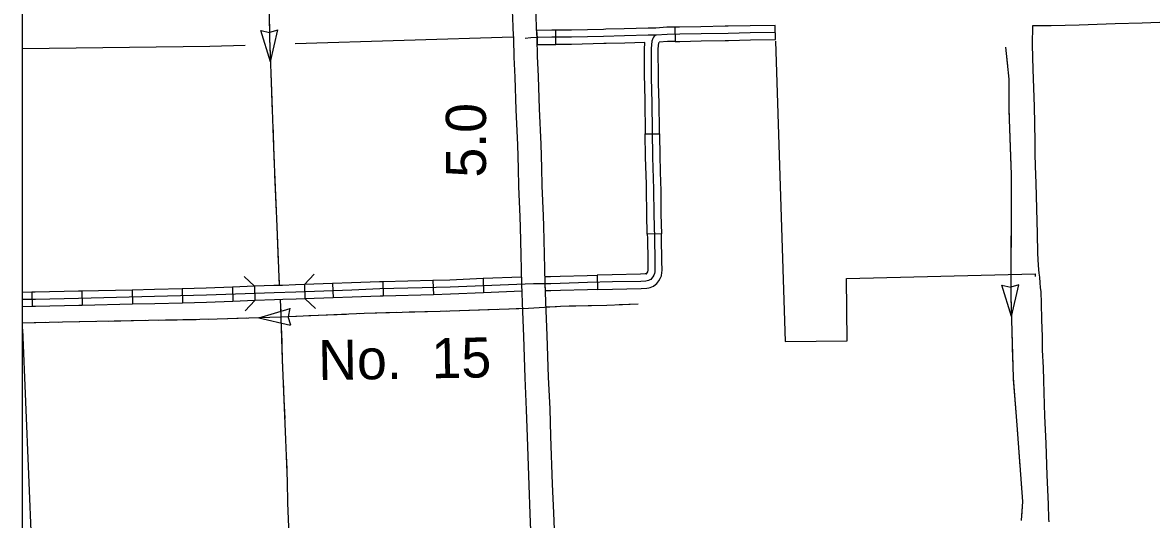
# Model space of a CAD drawing. Extents: x -117616 to 64730, y 54117 to 789866.
# Drawn here: x 62347.4 to 62585, y 54731.4 to 54836.1 of the extents above; entities that cross this region are included whole.
import ezdxf

# ---------------------------------------------------------------- set-up
doc = ezdxf.new("R2010")
doc.units = 0
for name, color, linetype in [('10', 7, 'Continuous'), ('31', 7, 'Continuous'), ('32', 7, 'Continuous'), ('33', 7, 'Continuous'), ('34', 7, 'Continuous'), ('38', 7, 'Continuous'), ('43', 7, 'Continuous'), ('48', 7, 'Continuous'), ('5', 7, 'Continuous'), ('6', 7, 'Continuous'), ('R_No Plot', 7, 'Continuous')]:
    doc.layers.add(name, color=color, linetype=linetype)

msp = doc.modelspace()

# ---------------------------------------------------------------- linework, layer by layer
at = {"layer": '10'}
for points in [[(62455.71, 54832.86), (62455.58, 54834.94), (62455.49, 54837.59), (62455.42, 54838.97), (62455.39, 54840.33), (62455.28, 54843.01), (62455.03, 54848.86), (62454.92, 54851.89), (62454.84, 54854.63), (62454.71, 54858.54), (62454.57, 54861.37), (62454.52, 54862.77)], [(62449.52, 54862.7), (62449.57, 54861.27), (62449.71, 54858.44), (62449.84, 54854.59), (62449.92, 54851.84), (62450.03, 54848.78), (62450.28, 54842.91), (62450.39, 54840.27), (62450.42, 54838.88), (62450.5, 54837.49), (62450.58, 54834.82), (62450.72, 54832.66)], [(62450.72, 54832.66), (62450.82, 54828.83), (62451.01, 54824.59), (62451.2, 54817.72), (62451.56, 54810.33), (62451.72, 54805.37), (62451.8, 54801.59), (62452.05, 54795.2), (62452.15, 54793.02), (62452.29, 54787.22), (62452.44, 54781.04)], [(62457.44, 54781.17), (62457.29, 54787.34), (62457.15, 54793.2), (62457.04, 54795.42), (62456.8, 54801.74), (62456.72, 54805.5), (62456.55, 54810.53), (62456.2, 54817.91), (62456.01, 54824.77), (62455.82, 54829.01), (62455.71, 54832.86)], [(62452.44, 54781.04), (62452.66, 54775.25), (62452.87, 54769.99), (62453.13, 54761.25), (62453.43, 54754.52), (62453.61, 54748.81), (62453.97, 54738.69), (62454.21, 54732.61), (62454.41, 54727.36)], [(62459.41, 54727.55), (62459.21, 54732.81), (62458.97, 54738.88), (62458.61, 54748.98), (62458.43, 54754.71), (62458.13, 54761.44), (62457.86, 54770.17), (62457.65, 54775.44), (62457.44, 54781.17)]]:
    msp.add_lwpolyline(points, dxfattribs=at)
at = {"layer": '31'}
for p, q in [((62459.63, 54831.53), (62459.63, 54834.53)), ((62484.72, 54835.14), (62484.74, 54832.14)), ((62505.9, 54832.53), (62505.8, 54835.53)), ((62484.74, 54832.14), (62484.74, 54832.14)), ((62478.45, 54812.68), (62481.45, 54812.71)), ((62481.45, 54812.71), (62481.45, 54812.71)), ((62481.9, 54791.62), (62478.9, 54791.54)), ((62481.9, 54791.62), (62478.9, 54791.54)), ((62468.37, 54782.89), (62468.45, 54779.89)), ((62468.37, 54782.89), (62468.45, 54779.89))]:
    msp.add_line(p, q, dxfattribs=at)
for points in [[(62459.63, 54834.53), (62458.83, 54834.53), (62455.61, 54834.47), (62455.71, 54832.91), (62455.75, 54831.48)], [(62470.15, 54834.7), (62469.68, 54834.69), (62462.93, 54834.53), (62459.63, 54834.53)], [(62480.71, 54834.97), (62479.05, 54834.93), (62474.06, 54834.79), (62470.15, 54834.7)], [(62484.72, 54835.14), (62483.04, 54835.13), (62480.71, 54834.97)], [(62495.27, 54835.33), (62490.19, 54835.25), (62485.71, 54835.14), (62484.72, 54835.14)], [(62505.8, 54835.53), (62500.55, 54835.46), (62495.9, 54835.34), (62495.27, 54835.33)], [(62480.74, 54833.47), (62479.09, 54833.43), (62474.1, 54833.29), (62469.71, 54833.19), (62462.95, 54833.03), (62458.84, 54833.03), (62455.92, 54832.98), (62454.39, 54832.9), (62453.21, 54832.76)], [(62480.74, 54833.47), (62480.43, 54833.3), (62480.21, 54833.06), (62480.06, 54832.78), (62479.89, 54832.17), (62479.78, 54831.43), (62479.71, 54830.63), (62479.74, 54824.54), (62479.89, 54819.11), (62479.94, 54813.33), (62480.01, 54807.77), (62480.24, 54801.03), (62480.28, 54795.71), (62480.42, 54790.76), (62480.49, 54785.89), (62480.51, 54783.95), (62480.49, 54783.62), (62480.42, 54783.22), (62480.27, 54782.88), (62480.07, 54782.54), (62479.77, 54782.17), (62479.62, 54782.01), (62479.47, 54781.89), (62479.12, 54781.76), (62478.61, 54781.67), (62477.52, 54781.6), (62471.56, 54781.48), (62466.3, 54781.33), (62460.58, 54781.18), (62458.57, 54781.1), (62454.94, 54781.1)], [(62478.35, 54831.91), (62474.14, 54831.79), (62470.22, 54831.7)], [(62478.33, 54831.91), (62478.29, 54831.61), (62478.21, 54830.7), (62478.24, 54824.52), (62478.28, 54823.21)], [(62505.85, 54834.03), (62500.58, 54833.96), (62495.93, 54833.84), (62490.21, 54833.75), (62485.73, 54833.64), (62483.1, 54833.63), (62480.74, 54833.47)], [(62481.28, 54823.29), (62481.24, 54824.56), (62481.21, 54830.57), (62481.27, 54831.25), (62481.36, 54831.85), (62481.4, 54832.01)], [(62484.74, 54832.14), (62483.15, 54832.13), (62481.42, 54832.01)], [(62484.74, 54832.14), (62485.75, 54832.14), (62490.24, 54832.25), (62495.32, 54832.33)], [(62495.32, 54832.33), (62495.96, 54832.34), (62500.61, 54832.46), (62505.9, 54832.53)], [(62455.75, 54831.48), (62458.85, 54831.53), (62459.63, 54831.53)], [(62470.22, 54831.7), (62469.75, 54831.69), (62462.97, 54831.53), (62459.63, 54831.53)], [(62478.28, 54823.21), (62478.39, 54819.08), (62478.44, 54813.32), (62478.45, 54812.68)], [(62481.45, 54812.71), (62481.44, 54813.35), (62481.39, 54819.13), (62481.28, 54823.29)], [(62478.7, 54802.09), (62478.51, 54807.74), (62478.45, 54812.68)], [(62481.45, 54812.71), (62481.51, 54807.81), (62481.7, 54802.19)], [(62478.9, 54791.54), (62478.79, 54795.69), (62478.74, 54801), (62478.7, 54802.09)], [(62481.7, 54802.19), (62481.74, 54801.07), (62481.78, 54795.74), (62481.9, 54791.62)], [(62478.9, 54791.54), (62478.92, 54790.73), (62478.99, 54785.87), (62479.01, 54783.99), (62479, 54783.8), (62478.97, 54783.65), (62478.94, 54783.57), (62478.83, 54783.4), (62478.68, 54783.21), (62478.7, 54783.21)], [(62479.22, 54780.26), (62479.5, 54780.31), (62480.23, 54780.56), (62480.63, 54780.91), (62480.9, 54781.17), (62481.31, 54781.69), (62481.61, 54782.2), (62481.87, 54782.79), (62481.98, 54783.44), (62482.01, 54783.91), (62481.99, 54785.91), (62481.92, 54790.79), (62481.9, 54791.62)], [(62457.5, 54779.6), (62457.44, 54781.17), (62457.41, 54782.6), (62457.86, 54782.6)], [(62457.86, 54782.6), (62458.54, 54782.6), (62460.54, 54782.68), (62466.26, 54782.83), (62468.37, 54782.89)], [(62478.7, 54783.21), (62478.43, 54783.16), (62477.46, 54783.1), (62471.52, 54782.98), (62468.37, 54782.89)], [(62457.85, 54779.6), (62457.5, 54779.6)], [(62468.45, 54779.89), (62466.34, 54779.83), (62460.63, 54779.68), (62458.6, 54779.6), (62457.85, 54779.6)], [(62468.45, 54779.89), (62471.59, 54779.98), (62477.58, 54780.1), (62478.79, 54780.18), (62479.22, 54780.26)]]:
    msp.add_lwpolyline(points, dxfattribs=at)
at = {"layer": '32'}
for p, q in [((62444.33, 54782.17), (62444.45, 54779.17)), ((62370.48, 54779.77), (62370.55, 54776.77)), ((62381.03, 54780.03), (62381.11, 54777.03)), ((62391.57, 54780.37), (62391.68, 54777.37)), ((62396.21, 54780.55), (62396.31, 54777.55)), ((62406.77, 54780.91), (62406.86, 54777.91)), ((62412.68, 54781.13), (62412.78, 54778.13)), ((62423.24, 54781.5), (62423.32, 54778.5)), ((62433.8, 54781.78), (62433.88, 54778.78)), ((62349.37, 54779.29), (62349.43, 54776.29)), ((62359.92, 54779.54), (62359.99, 54776.54))]:
    msp.add_line(p, q, dxfattribs=at)
for points in [[(62444.33, 54782.17), (62437.37, 54781.88), (62433.8, 54781.78)], [(62452.41, 54782.5), (62444.33, 54782.17)], [(62454.94, 54781.1), (62437.42, 54780.38), (62422.62, 54779.99), (62416.73, 54779.77), (62404.93, 54779.34), (62400.37, 54779.2), (62386.1, 54778.66), (62375.19, 54778.38), (62359.22, 54778.02), (62350.12, 54777.81), (62347.42, 54777.75)], [(62370.48, 54779.77), (62359.92, 54779.54)], [(62381.03, 54780.03), (62375.16, 54779.88), (62370.48, 54779.77)], [(62391.57, 54780.37), (62386.06, 54780.16), (62381.03, 54780.03)], [(62396.21, 54780.55), (62391.57, 54780.37)], [(62402.13, 54780.76), (62400.32, 54780.7), (62396.21, 54780.55)], [(62406.77, 54780.91), (62404.88, 54780.84), (62402.13, 54780.76)], [(62412.68, 54781.13), (62406.77, 54780.91)], [(62423.24, 54781.5), (62422.57, 54781.48), (62416.68, 54781.27), (62412.68, 54781.13)], [(62433.8, 54781.78), (62423.24, 54781.5)], [(62349.37, 54779.29), (62347.42, 54779.25)], [(62359.92, 54779.54), (62359.18, 54779.52), (62350.09, 54779.31), (62349.37, 54779.29)], [(62391.68, 54777.37), (62386.15, 54777.17), (62381.11, 54777.03)], [(62396.31, 54777.55), (62391.68, 54777.37)], [(62402.22, 54777.76), (62400.42, 54777.7), (62396.31, 54777.55)], [(62406.86, 54777.91), (62404.98, 54777.84), (62402.22, 54777.76)], [(62412.78, 54778.13), (62406.86, 54777.91)], [(62423.32, 54778.5), (62422.67, 54778.49), (62416.79, 54778.27), (62412.78, 54778.13)], [(62433.88, 54778.78), (62423.32, 54778.5)], [(62444.45, 54779.17), (62437.47, 54778.88), (62433.88, 54778.78)], [(62452.5, 54779.5), (62444.45, 54779.17)], [(62349.43, 54776.29), (62347.42, 54776.25)], [(62359.99, 54776.54), (62359.25, 54776.52), (62350.16, 54776.31), (62349.43, 54776.29)], [(62370.55, 54776.77), (62359.99, 54776.54)], [(62381.11, 54777.03), (62375.23, 54776.88), (62370.55, 54776.77)]]:
    msp.add_lwpolyline(points, dxfattribs=at)
at = {"layer": '33'}
msp.add_lwpolyline([(62560.02, 54835.47), (62563.9, 54835.49), (62569.77, 54835.66), (62577.34, 54835.89), (62583.04, 54836.06), (62588.57, 54836.26), (62598.36, 54836.6), (62605.12, 54836.85), (62612.17, 54837.1), (62616.88, 54837.37), (62623.1, 54837.64), (62632.03, 54838.03), (62634.71, 54838.21), (62637.23, 54838.23), (62642.48, 54838.35), (62650.03, 54838.6), (62656.67, 54838.77), (62662.27, 54838.95), (62663.3, 54839), (62663.84, 54839.07), (62664.24, 54839.14), (62664.54, 54839.24), (62664.71, 54839.34), (62664.84, 54839.42)], dxfattribs=at)
at = {"layer": '34'}
msp.add_lwpolyline([(62563.45, 54730.92), (62563.4, 54731.57), (62563.31, 54734.69), (62563.07, 54740.77), (62562.83, 54747.44), (62562.6, 54753.27), (62562.53, 54755.68), (62562.34, 54760.68), (62562.27, 54763.43), (62562.1, 54767.11), (62562.04, 54770), (62561.93, 54773.48), (62561.83, 54777.02), (62561.77, 54779.39), (62561.65, 54780.29), (62561.55, 54781.28), (62561.48, 54782.49), (62561.37, 54783.34), (62561.24, 54784.91), (62561.12, 54787.52), (62561.05, 54791.71), (62560.88, 54796.86), (62560.77, 54802.29), (62560.62, 54805.88), (62560.54, 54808.44), (62560.51, 54810.92), (62560.45, 54814.89), (62560.38, 54818.4), (62560.24, 54822.37), (62560.09, 54826.22), (62559.99, 54831.4), (62560.02, 54835.47)], dxfattribs=at)
at = {"layer": '38'}
for points in [[(62394.03, 54782.61), (62396.22, 54780.56)], [(62406.77, 54780.91), (62408.81, 54783.1)], [(62396.31, 54777.56), (62394.25, 54775.37)], [(62409.06, 54775.87), (62406.87, 54777.91)]]:
    msp.add_lwpolyline(points, dxfattribs=at)
at = {"layer": '43'}
for p, q in [((62399.6, 54827.88), (62397.58, 54834.43)), ((62397.61, 54834.47), (62399.38, 54834.03)), ((62401.16, 54834.53), (62399.41, 54834.03)), ((62399.6, 54827.88), (62401.13, 54834.57)), ((62553.55, 54780.78), (62555.39, 54780.36)), ((62555.52, 54774.2), (62553.55, 54780.78)), ((62557.1, 54780.88), (62555.42, 54780.36)), ((62555.52, 54774.2), (62557.1, 54780.88)), ((62397.15, 54773.91), (62403.71, 54775.91)), ((62403.7, 54775.93), (62403.3, 54774.14)), ((62397.15, 54773.91), (62403.84, 54772.36)), ((62403.85, 54772.38), (62403.3, 54774.12))]:
    msp.add_line(p, q, dxfattribs=at)
for points in [[(62397.76, 54884.6), (62398.11, 54878.07), (62398.29, 54869.75), (62398.59, 54861.73), (62398.81, 54855.9), (62399.16, 54848.58), (62399.42, 54832.77), (62399.76, 54823.62), (62400.29, 54807.9), (62400.94, 54793.13), (62401.42, 54780.73)], [(62399.37, 54835.79), (62399.42, 54832.77), (62399.6, 54827.88)], [(62554.31, 54830.91), (62555, 54824.2), (62555, 54817.68), (62555.5, 54804.14), (62555.4, 54778.36), (62555.89, 54761.27), (62556.68, 54751.29), (62557.87, 54735.19), (62557.57, 54731.24)], [(62554.31, 54830.91), (62554.72, 54826.97)], [(62399.7, 54825.24), (62399.76, 54823.62), (62399.84, 54821.28)], [(62554.99, 54824.35), (62555, 54824.2), (62555, 54817.68), (62555.05, 54816.43)], [(62399.84, 54821.28), (62399.97, 54817.32)], [(62400.06, 54814.68), (62400.29, 54807.9), (62400.34, 54806.77)], [(62555.15, 54813.79), (62555.43, 54805.88)], [(62400.45, 54804.13), (62400.8, 54796.22)], [(62555.49, 54803.24), (62555.46, 54795.32)], [(62400.92, 54793.58), (62400.94, 54793.13), (62401.23, 54785.67)], [(62555.45, 54792.68), (62555.42, 54784.76)], [(62401.33, 54783.03), (62401.42, 54780.73)], [(62555.41, 54782.12), (62555.4, 54778.36), (62555.52, 54774.2)], [(62401.64, 54777.74), (62401.74, 54776.2), (62402.06, 54765.04), (62402.44, 54756.74), (62402.78, 54748.22), (62402.89, 54744.83), (62403.13, 54739.51), (62403.16, 54734.87), (62403.58, 54724.83), (62404.01, 54716.52), (62404.38, 54704.16), (62404.62, 54694.66), (62405.16, 54680.66), (62405.4, 54674.07), (62405.66, 54668.09), (62406.24, 54652.97), (62406.85, 54637.06), (62407.48, 54619.5)], [(62401.64, 54777.74), (62401.74, 54776.2), (62401.77, 54775.32)], [(62453.87, 54775.9), (62435.32, 54775.27), (62419.34, 54774.81), (62401.7, 54774.07), (62388.36, 54773.61), (62355.83, 54772.98), (62347.42, 54772.81)], [(62426.17, 54775.01), (62419.34, 54774.81), (62418.25, 54774.76)], [(62436.72, 54775.32), (62435.32, 54775.27), (62428.81, 54775.08)], [(62447.28, 54775.68), (62439.36, 54775.41)], [(62452.63, 54775.86), (62449.91, 54775.77)], [(62476.95, 54776.82), (62470.4, 54776.52), (62460.6, 54776.31), (62453.87, 54775.9)], [(62459.8, 54776.26), (62457.63, 54776.13)], [(62470.36, 54776.52), (62462.44, 54776.35)], [(62476.95, 54776.82), (62472.99, 54776.64)], [(62352.28, 54772.9), (62347.42, 54772.81)], [(62362.84, 54773.11), (62355.83, 54772.98), (62354.92, 54772.96)], [(62373.4, 54773.32), (62365.48, 54773.16)], [(62383.95, 54773.52), (62376.04, 54773.37)], [(62390.55, 54773.68), (62388.36, 54773.61), (62386.59, 54773.57)], [(62394.51, 54773.82), (62390.55, 54773.68)], [(62405.06, 54774.21), (62401.7, 54774.07), (62397.15, 54773.91)], [(62415.61, 54774.65), (62407.7, 54774.32)], [(62401.89, 54771.14), (62402.06, 54765.04), (62402.14, 54763.23)], [(62555.59, 54771.56), (62555.71, 54767.6)], [(62555.71, 54767.6), (62555.82, 54763.65)], [(62402.26, 54760.59), (62402.44, 54756.74), (62402.6, 54752.68)], [(62555.91, 54761.01), (62556.54, 54753.11)], [(62402.71, 54750.04), (62402.78, 54748.22), (62402.89, 54744.83), (62403.01, 54742.13)], [(62556.74, 54750.48), (62557.32, 54742.58)], [(62403.13, 54739.49), (62403.16, 54734.87), (62403.3, 54731.57)], [(62557.52, 54739.95), (62557.87, 54735.19), (62557.63, 54732.05)]]:
    msp.add_lwpolyline(points, dxfattribs=at)
at = {"layer": '5'}
for points in [[(62450.69, 54833.01), (62404.81, 54831.63)], [(62394.3, 54831.32), (62386.8, 54831.09), (62347.42, 54830.6)], [(62347.42, 54771.56), (62349.3, 54725.61)]]:
    msp.add_lwpolyline(points, dxfattribs=at)
at = {"layer": '6'}
msp.add_lwpolyline([(62505.91, 54832.21), (62507.92, 54768.94), (62520.95, 54769.1), (62520.85, 54782.19), (62560.51, 54783.16), (62560.53, 54782.64)], dxfattribs=at)
at = {"layer": 'R_No Plot'}
msp.add_lwpolyline([(62347.42, 55314.94), (63854.85, 55314.94), (63854.85, 54389.3), (62347.42, 54389.3)], close=True, dxfattribs=at)

# ---------------------------------------------------------------- texts
at = {"layer": '43'}
msp.add_text('No.  15', height=8.448, rotation=0.94, dxfattribs=at).set_placement((62409.7, 54760.78))
at = {"layer": '48'}
msp.add_text('5.0', height=8.448, rotation=89.9891, dxfattribs=at).set_placement((62444.95, 54803.46))

doc.saveas('drawing.dxf')
